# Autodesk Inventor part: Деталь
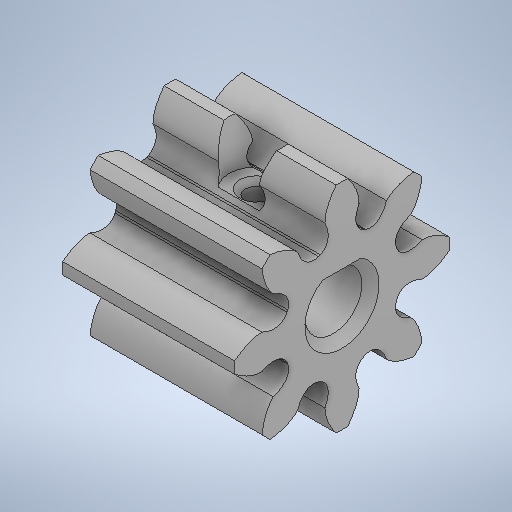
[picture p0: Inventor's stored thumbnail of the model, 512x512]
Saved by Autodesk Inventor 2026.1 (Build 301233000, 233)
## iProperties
Company: UNSPECIFIED
Created: 1900-01
Part Number: Деталь
Material: Типовые
Description: STEP AP203
Document SubType Name: Modeling
Designer: Yury Melnikov
Density: 1 g/cm^3
Appearance: По умолчанию
Sending System: C3D Toolkit
Preprocessor: C3D Converter
Title: Äåòàëü
Author: UNSPECIFIED
Revision Number: ANYUNSPECIFIED
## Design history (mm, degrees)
node "Исправленная геометрия1"
  sketch "3D эскиз1"
  node "3D эскиз2"
  node "3D эскиз3"
  node "3D эскиз4"
  sketch "3D эскиз5"
  node "3D эскиз6"
feature "БазТело1"
sketch "Эскиз1"
  geometry: L1 (-1.549, 2.15)-(1.549, 2.15); A1 r 2.65 centre (0, 0) between (-1.549, 2.15) and (1.549, 2.15); 1 further point
  constraints: 2 end point, 2 point on circle, 1 centre point, 1 coincident, 1 horizontal
  dimensions: "d0" = 5.3 diameter of A1; "d1" = 4.8 dimension on A1 L1
extrude "Выдавливание1" cut sketch "Эскиз1" distance "d2" = 20; taper "d3" = 0 deg
sketch "Эскиз2" dims "d0" = 5.3, "d1" = 4.8
  geometry: L1 (-16, 8.992)-(0, 8.992) reference; C1 r 1 at (-8, 1.549); 2 further points
  constraints: 1 centre point, 1 horizontal alignment, 1 midpoint, 1 vertical alignment
  dimensions: "d4" = 2 diameter of C1
extrude "Выдавливание2" cut sketch "Эскиз2" distance "d5" = 20; taper "d6" = 0 deg
node "РабПлоскость1"
sketch "Эскиз3"
  geometry: C1 r 1 at (-8, 1.549) reference; C2 r 2.5 at (-8, 1.549); 5 further points
  constraints: 2 horizontal alignment, 2 vertical alignment, 1 centre point, 1 coincident
  dimensions: "d8" = 5 diameter of C2
extrude "Выдавливание3" cut sketch "Эскиз3" distance "d9" = 20; taper "d10" = 0 deg
chamfer "Фаска1" distance "d11" = 0.5; stored, may be unused: second distance "d12" = 2, angle "d13" = 45 deg
chamfer "Фаска2" distance "d14" = 0.8; stored, may be unused: second distance "d15" = 2, angle "d16" = 45 deg
node "Твердое тело1"
node "Спроецированная петля1"
other parameters: "d7" = -3.25
